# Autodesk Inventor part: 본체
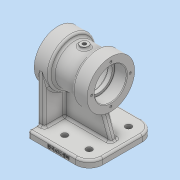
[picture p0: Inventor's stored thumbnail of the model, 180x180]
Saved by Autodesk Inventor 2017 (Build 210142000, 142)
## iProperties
Part Number: 본체
Material: 일반
Document SubType Name: Modeling
Designer: mrc
Density: 1 g/cm^3
Appearance: 기본값
Mass: 268.503 g
Surface Area: 642.533 cm^2
Volume: 268.503 cm^3
Author: mrc
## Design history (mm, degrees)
sketch "스케치1"
  geometry: L1 (-39, 0)-(39, 0); L2 (-39, 0)-(-39, 35); L3 (-39, 35)-(-17, 35); L4 (-17, 35)-(-17, 29); L5 (-17, 29)-(17, 29); L6 (17, 29)-(17, 35); L7 (17, 35)-(39, 35); L8 (39, 35)-(39, 0); 2 further points
  constraints: 16 end point, 5 perpendicular, 2 midpoint, 2 point on line, 1 coincident, 1 horizontal, 1 vertical
  dimensions: "d0" = 78 distance of L1.start L1.end; "d1" = 70 diameter of L7 L1; "d2" = 58 diameter of L5 L1; "d3" = 22 distance of L6.end L7.end; "d4" = 22 distance of L2.end L3.end
revolve "회전1" sketch "스케치1" stored, may be unused: angle "d5" = 90 deg
sketch "스케치2"
  geometry: C1 r 23.5 at (0, 0); 1 further point
  constraints: 1 centre point, 1 coincident
  dimensions: "d6" = 47 diameter of C1
extrude "돌출1" cut sketch "스케치2" distance "d7" = 18; taper "d8" = 0 deg
sketch "스케치3"
  geometry: C1 r 20 at (0, 0); 1 further point
  constraints: 1 centre point, 1 coincident
  dimensions: "d9" = 40 diameter of C1
extrude "돌출2" cut sketch "스케치3" distance "d10" = 6; taper "d11" = 0 deg
sketch "스케치4"
  geometry: C1 r 23 at (0, 0); 1 further point
  constraints: 1 centre point, 1 coincident
  dimensions: "d12" = 46 diameter of C1
extrude "돌출3" cut sketch "스케치4" distance "d13" = 30; taper "d14" = 0 deg
node "작업 평면1"
sketch "스케치5"
  geometry: C1 r 6 at (0, 0); 1 further point
  constraints: 1 centre point, 1 coincident
  dimensions: "d16" = 12 diameter of C1
extrude "돌출4" join sketch "스케치5" stored distance "d17" = 30; taper "d18" = 0 deg
sketch "스케치6"
  geometry: C1 r 6 at (0, 0) reference; 2 further points
  constraints: 1 coincident
hole "구멍1" sketch "스케치6" at (0, 0) diameter "d19" = 5.188; stored, may be unused: countersink angle "d23" = 90 deg, drill point angle "d25" = 118 deg; dims "d20" = 12, "d21" = 4, "d22" = 2, "d24" = 16
sketch "스케치7" dims "d26" = 57
  geometry: 3 further points
  constraints: 2 vertical alignment, 1 coincident, 2 other
hole "구멍2" sketch "스케치7" at (0, 28.5) diameter "d27" = 3.242; stored, may be unused: countersink angle "d31" = 90 deg, drill point angle "d33" = 118 deg; dims "d28" = 10, "d29" = 4, "d30" = 2, "d32" = 12
node "작업 평면2"
sketch "스케치8"
  geometry: L1 (-34, -49)-(56, -49); L2 (56, -49)-(56, 49); L3 (56, 49)-(-34, 49); L4 (-34, 49)-(-34, -49); L5 (-34, -49)-(56, 49); L6 (56, -49)-(-34, 49); L7 (-39, -35)-(-39, 35) reference; 3 further points
  constraints: 12 end point, 3 midpoint, 2 parallel, 1 horizontal, 1 horizontal alignment, 1 perpendicular
  dimensions: "d38" = 90 distance of L3.end L2.end; "d39" = 98 distance of L1.end L2.end; "d40" = 5 distance between parallel lines of L7 L4
extrude "돌출5" join sketch "스케치8" distance "d41" = 10; taper "d42" = 0 deg
sketch "스케치9"
  geometry: L1 (-34, 49)-(-34, -49) reference; L2 (-34, -35)-(-34, 35); L3 (-34, 35)-(-24, 35); L4 (-24, 35)-(-24, -35); L5 (-24, -35)-(-34, -35); 3 further points
  constraints: 8 end point, 2 midpoint, 2 perpendicular, 2 point on line, 1 coincident
  dimensions: "d43" = 70 distance of L2.start L2.end; "d45" = 10 distance of L2.end L3.end; "d46" = 70 distance of L3.end L4.end
sketch "스케치10"
  geometry: L1 (-34, 49)-(-34, -49) reference; L2 (56, 49)-(-34, 49) reference; C1 r 4.5 at (36, 29); C2 r 4.5 at (0, 29); 1 further point
  constraints: 2 centre point
  dimensions: "d47" = 9 diameter of C1; "d48" = 9 diameter of C2; "d49" = 70 distance from line of L1 C1.centre; "d50" = 36 distance of C2.centre C1.centre; "d51" = 20 distance from line of L2 C1.centre; "d52" = 20 distance from line of L2 C2.centre
extrude "돌출6" cut sketch "스케치10" stored distance "d53" = 0; taper "d54" = 0 deg
fillet "모깎기1" dims "d55" = 20
fillet "모깎기2" dims "d56" = 3
extrude "돌출7" join sketch "스케치9" stored distance "d57" = 10; taper "d58" = 0 deg
sketch "스케치11"
  geometry: L1 (-56, -73)-(-56, -80) reference; L2 (-53, -70)-(-36, -70) reference; L3 (-44, -70)-(-31.261, -35); L4 (-17, -35)-(-39, -35) reference; 1 further point
  constraints: 2 end point, 2 point on line
  dimensions: "d60" = 12 distance from line of L1 L3.start; "d61" = 70 deg angle of L2 L3
feature "리브1" sketch "스케치11" dims "d62" = 1, "d63" = 10, "d64" = 0, "d65" = 0, "d66" = 1, "d67" = 1
sketch "스케치12"
  geometry: L1 (0, 0)-(70, 0) reference; L2 (0, 0)-(0, 7) reference; 2 further points
  constraints: 1 other
  dimensions: "d68" = 4 distance from line of L1 point (45, 4); "d69" = 45 distance from line of L2 point (45, 4)
feature "엠보싱1" sketch "스케치12" dims "d70" = 0.5, "d71" = 0
fillet "모깎기3" dims "d72" = 3
fillet "모깎기4" dims "d73" = 3
chamfer "모따기1" distance "d74" = 1; stored, may be unused: second distance "d75" = 2, angle "d76" = 45 deg
fillet "모깎기5" dims "d77" = 3
fillet "모깎기6" dims "d78" = 0.3
fillet "모깎기7" dims "d79" = 3
fillet "모깎기8" dims "d80" = 3
fillet "모깎기9" dims "d81" = 3
fillet "모깎기10" dims "d82" = 3
node "솔리드1"
mirror "미러1"
pattern_circular "원형 패턴1" dims angle "d35" = 360 deg
mirror "미러2"
mirror "미러3"
other parameters: "d15" = 32
